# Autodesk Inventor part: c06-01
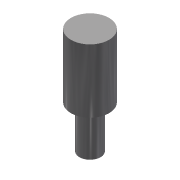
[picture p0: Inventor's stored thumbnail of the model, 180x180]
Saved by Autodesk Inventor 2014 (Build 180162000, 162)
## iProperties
Created: 2013-03
Part Number: c06-01
Material: Steel, Carbon
Document SubType Name: Modeling
Designer: Thom Tremblay
Density: 7.87 g/cm^3
Appearance: Semi-Polished
Author: Thom Tremblay
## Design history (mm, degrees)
sketch "Sketch1"
  geometry: C1 r 9 at (0, 0); 1 further point
  constraints: 1 centre point, 1 coincident
  dimensions: "d0" = 18 diameter of C1
extrude "Extrusion1" new body sketch "Sketch1" distance "d1" = 30; taper "d2" = 0 deg
sketch "Sketch2"
  geometry: C1 r 9 at (0, 0) reference; C2 r 5 at (0, 0)
  constraints: 1 centre point, 1 coincident
  dimensions: "d3" = 10 diameter of C2
extrude "Extrusion2" join sketch "Sketch2" distance "d4" = 20; taper "d5" = 0 deg
body "Solid1"
